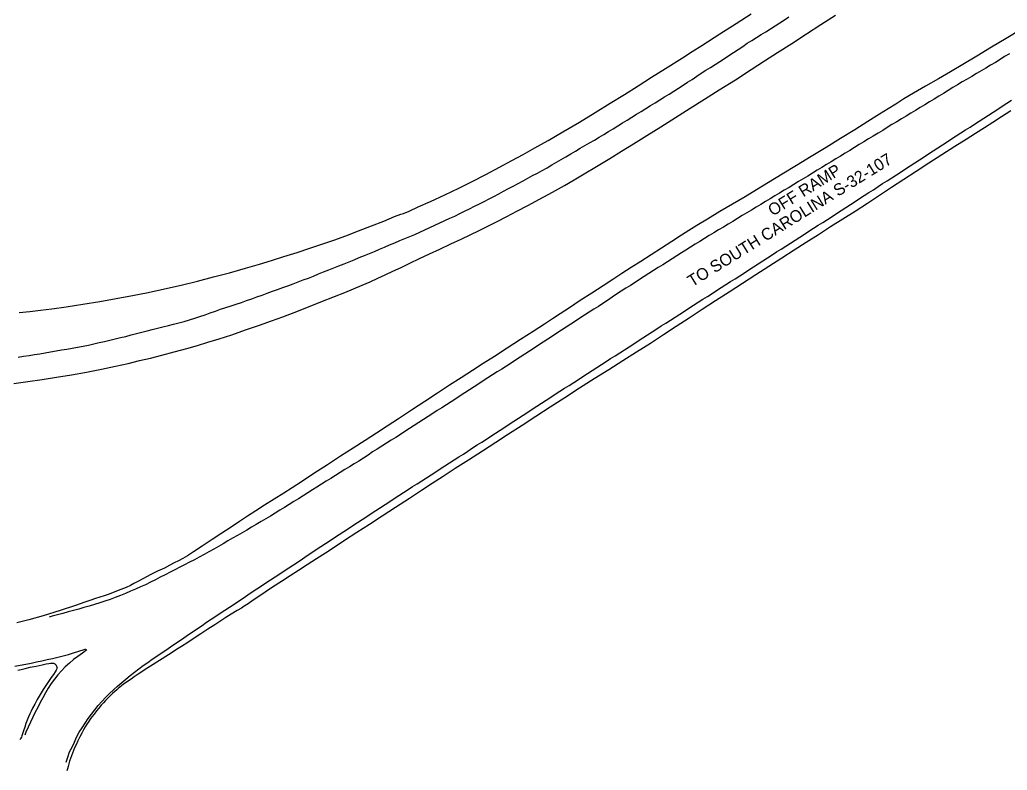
# Model space of a CAD drawing. Extents: x 1961683 to 1977751, y 798292 to 805767.
# Drawn here: x 1963000.6 to 1963450.9, y 799966.6 to 800308.9 of the extents above; entities that cross this region are included whole.
import ezdxf

# ---------------------------------------------------------------- set-up
doc = ezdxf.new("R2010")
doc.units = 0
for name, color, linetype in [('RD_EX_Conc', 7, 'Continuous'), ('RD_EX_Road', 7, 'Continuous'), ('RD_EX_Road_Paint', 7, 'Continuous'), ('RD_TX_RoadID', 7, 'Continuous')]:
    doc.layers.add(name, color=color, linetype=linetype)

msp = doc.modelspace()

# ---------------------------------------------------------------- linework, layer by layer
at = {"layer": 'RD_EX_Conc'}
msp.add_lwpolyline([(1962999.74, 800012.29), (1963001.27, 800012.63), (1963003.09, 800013.05), (1963005.34, 800013.57), (1963008.12, 800014.17), (1963010.78, 800014.72), (1963012.63, 800015.09), (1963013.86, 800015.32), (1963014.66, 800015.45), (1963015.21, 800015.5), (1963015.68, 800015.51), (1963015.89, 800015.47), (1963016.11, 800015.41), (1963016.34, 800015.3), (1963016.56, 800015.15), (1963016.95, 800014.84), (1963017.09, 800014.7), (1963017.19, 800014.58), (1963017.28, 800014.44), (1963017.45, 800014.09), (1963017.54, 800013.86), (1963017.6, 800013.62), (1963017.63, 800013.38), (1963017.61, 800013.13), (1963017.56, 800012.88), (1963017.45, 800012.6), (1963017.29, 800012.28), (1963016.78, 800011.48), (1963016.01, 800010.37), (1963014.94, 800008.87), (1963013.74, 800007.13), (1963012.58, 800005.35), (1963011.35, 800003.39), (1963009.97, 800001.13), (1963008.61, 799998.82), (1963007.44, 799996.71), (1963006.48, 799994.92), (1963005.79, 799993.58), (1963005.2, 799992.35), (1963004.58, 799990.92), (1963003.97, 799989.4), (1963003.42, 799987.9), (1963002.9, 799986.34), (1963002.38, 799984.65), (1963001.93, 799983.19), (1963001.63, 799982.31), (1963001.41, 799981.75), (1963001.19, 799981.28), (1963001.06, 799981.08), (1963000.93, 799980.91), (1963000.77, 799980.77), (1963000.6, 799980.65)], dxfattribs=at)
at = {"layer": 'RD_EX_Road'}
for points in [[(1962997.89, 800143), (1963004.37, 800143.91), (1963010.81, 800144.86), (1963017.35, 800145.88), (1963024.16, 800147.02), (1963031.04, 800148.25), (1963037.83, 800149.58), (1963044.25, 800150.93), (1963050.02, 800152.22), (1963055.3, 800153.46), (1963060.24, 800154.63), (1963065.34, 800155.91), (1963071.08, 800157.43), (1963076.77, 800159), (1963081.7, 800160.42), (1963086.46, 800161.86), (1963091.62, 800163.46), (1963097.31, 800165.3), (1963103.62, 800167.44), (1963109.88, 800169.61), (1963115.38, 800171.54), (1963120.54, 800173.42), (1963125.78, 800175.43), (1963131.46, 800177.68), (1963137.95, 800180.24), (1963144.11, 800182.67), (1963148.81, 800184.53), (1963152.77, 800186.15), (1963156.7, 800187.82), (1963160.46, 800189.47), (1963163.89, 800191.01), (1963167.24, 800192.56), (1963170.77, 800194.22), (1963174.52, 800195.99), (1963178.55, 800197.92), (1963182.85, 800199.97), (1963187.42, 800202.13), (1963192.2, 800204.37), (1963197.13, 800206.66), (1963201.87, 800208.87), (1963206.07, 800210.85), (1963210.05, 800212.78), (1963214.11, 800214.81), (1963218.31, 800216.95), (1963222.68, 800219.21), (1963227.31, 800221.63), (1963232.29, 800224.22), (1963237.65, 800227.07), (1963243.47, 800230.27), (1963248.98, 800233.37), (1963253.44, 800235.95), (1963257.95, 800238.63), (1963263.63, 800242.03), (1963269.62, 800245.65), (1963275.06, 800248.97), (1963280.51, 800252.34), (1963286.53, 800256.11), (1963292.96, 800260.14), (1963299.62, 800264.33), (1963306.33, 800268.54), (1963312.85, 800272.65), (1963319.59, 800276.92), (1963326.93, 800281.61), (1963334.06, 800286.19), (1963340.18, 800290.13), (1963346.1, 800293.96), (1963352.65, 800298.18), (1963359.39, 800302.53), (1963365.89, 800306.73), (1963372.53, 800311.05)], [(1963000.35, 800175.41), (1963005.22, 800175.93), (1963010.14, 800176.49), (1963015.32, 800177.12), (1963021.75, 800178), (1963029.4, 800179.15), (1963037.09, 800180.42), (1963044.63, 800181.78), (1963051.98, 800183.15), (1963059.17, 800184.55), (1963066.58, 800186.14), (1963074.2, 800187.94), (1963081.65, 800189.77), (1963088.91, 800191.63), (1963096.27, 800193.58), (1963103.6, 800195.61), (1963109.97, 800197.44), (1963115.42, 800199.1), (1963121.11, 800200.89), (1963127.15, 800202.84), (1963132.9, 800204.74), (1963138.34, 800206.59), (1963143.77, 800208.48), (1963149.28, 800210.44), (1963155.07, 800212.59), (1963161.07, 800214.91), (1963166.64, 800217.14), (1963171.48, 800219.13), (1963174.37, 800220.25), (1963175.6, 800220.63), (1963178.12, 800221.67), (1963182.35, 800223.56), (1963187.86, 800226.09), (1963194.39, 800229.13), (1963200.77, 800232.18), (1963206.88, 800235.21), (1963213.07, 800238.4), (1963219.32, 800241.7), (1963224.98, 800244.73), (1963230.11, 800247.48), (1963235.55, 800250.5), (1963241.49, 800253.88), (1963248.27, 800257.83), (1963255.78, 800262.26), (1963263.03, 800266.64), (1963269.88, 800270.86), (1963276.38, 800274.89), (1963282.57, 800278.77), (1963288.74, 800282.69), (1963295.13, 800286.77), (1963302.78, 800291.64), (1963307.15, 800294.41), (1963311.59, 800297.22), (1963319.83, 800302.47), (1963327.26, 800307.24), (1963334.15, 800311.7)], [(1963456.89, 800304.32), (1963450.33, 800300.42), (1963443.7, 800296.44), (1963437.01, 800292.34), (1963430.65, 800288.46), (1963425, 800285.17), (1963419.53, 800282.04), (1963413.67, 800278.67), (1963408.17, 800275.46), (1963403.78, 800272.81), (1963400.06, 800270.51), (1963396.57, 800268.32), (1963392.58, 800265.81), (1963387.36, 800262.52), (1963381.33, 800258.75), (1963374.9, 800254.79), (1963368.25, 800250.7), (1963361.53, 800246.56), (1963354.82, 800242.45), (1963348.19, 800238.47), (1963342, 800234.75), (1963336.58, 800231.42), (1963331.33, 800228.21), (1963325.65, 800224.83), (1963319.86, 800221.41), (1963314.24, 800218.05), (1963309.36, 800215.08), (1963305.74, 800212.83), (1963302.3, 800210.63), (1963297.97, 800207.81), (1963293.2, 800204.7), (1963288.45, 800201.65), (1963283.83, 800198.7), (1963279.44, 800195.9), (1963275.2, 800193.2), (1963271.06, 800190.52), (1963266.6, 800187.64), (1963261.41, 800184.3), (1963256.1, 800180.84), (1963251.25, 800177.59), (1963247.03, 800174.73), (1963243.6, 800172.46), (1963239.89, 800170.05), (1963234.78, 800166.81), (1963228.9, 800163.06), (1963222.84, 800159.15), (1963217.03, 800155.39), (1963211.91, 800152.09), (1963207.01, 800148.95), (1963201.87, 800145.67), (1963196.54, 800142.24), (1963191.05, 800138.65), (1963185.31, 800134.86), (1963179.2, 800130.85), (1963173.29, 800126.98), (1963168.13, 800123.6), (1963163.23, 800120.39), (1963158.08, 800117.04), (1963152.65, 800113.52), (1963146.94, 800109.85), (1963140.96, 800105.99), (1963134.75, 800101.93), (1963129.1, 800098.25), (1963124.83, 800095.49), (1963121, 800093.06), (1963116.67, 800090.34), (1963112.27, 800087.56), (1963108.26, 800084.98), (1963104.48, 800082.51), (1963100.78, 800080.08), (1963096.95, 800077.55), (1963092.75, 800074.79), (1963088.33, 800071.86), (1963083.82, 800068.86), (1963079.85, 800066.25), (1963077.06, 800064.49), (1963074.93, 800063.25), (1963072.98, 800062.18), (1963071.07, 800061.18), (1963069.07, 800060.11), (1963066.65, 800058.87), (1963063.47, 800057.36), (1963060.08, 800055.73), (1963056.98, 800054.11), (1963054.43, 800052.72), (1963052.65, 800051.74), (1963051.06, 800050.93), (1963049.08, 800050.02), (1963046.72, 800049.04), (1963044.01, 800047.98), (1963041.35, 800046.98), (1963039.09, 800046.19), (1963037.09, 800045.52), (1963035.18, 800044.89), (1963033.03, 800044.16), (1963030.33, 800043.24), (1963026.01, 800041.79), (1963018.99, 800039.52), (1963011.24, 800037.12), (1963004.74, 800035.27), (1962999.34, 800033.91)], [(1963452.55, 800267.45), (1963448.32, 800264.71), (1963444.28, 800262.09), (1963440.47, 800259.63), (1963436.46, 800257.1), (1963432.09, 800254.38), (1963426.95, 800251.11), (1963421.07, 800247.3), (1963415.17, 800243.48), (1963409.38, 800239.73), (1963403.71, 800236.04), (1963398.15, 800232.4), (1963392.63, 800228.77), (1963387.12, 800225.16), (1963381.55, 800221.55), (1963375.91, 800217.97), (1963370.3, 800214.42), (1963364.75, 800210.9), (1963359.23, 800207.41), (1963353.73, 800203.92), (1963348.04, 800200.26), (1963342.17, 800196.43), (1963336.21, 800192.56), (1963330.19, 800188.66), (1963324.09, 800184.7), (1963317.91, 800180.68), (1963311.82, 800176.71), (1963305.85, 800172.82), (1963299.98, 800168.99), (1963294.17, 800165.19), (1963288.15, 800161.31), (1963281.89, 800157.35), (1963275.56, 800153.36), (1963269.16, 800149.33), (1963262.61, 800145.16), (1963255.91, 800140.86), (1963249.2, 800136.53), (1963242.54, 800132.22), (1963236, 800127.99), (1963229.63, 800123.89), (1963223.54, 800119.96), (1963217.67, 800116.15), (1963211.55, 800112.19), (1963205.18, 800108.08), (1963199.21, 800104.21), (1963193.73, 800100.65), (1963188.65, 800097.35), (1963183.81, 800094.21), (1963178.27, 800090.56), (1963172.02, 800086.41), (1963165.91, 800082.45), (1963160.05, 800078.74), (1963154.29, 800075.04), (1963148.71, 800071.39), (1963143.96, 800068.27), (1963140.02, 800065.66), (1963135.96, 800063), (1963131.72, 800060.25), (1963127.71, 800057.68), (1963123.95, 800055.31), (1963120, 800052.77), (1963115.93, 800050.1), (1963112.47, 800047.8), (1963109.66, 800045.91), (1963107.09, 800044.16), (1963104.75, 800042.55), (1963103, 800041.39), (1963101.73, 800040.61), (1963099.77, 800039.43), (1963097.1, 800037.82), (1963094.58, 800036.25), (1963092.26, 800034.75), (1963089.54, 800032.97), (1963086.37, 800030.91), (1963083.24, 800028.87), (1963080.21, 800026.88), (1963077.25, 800024.95), (1963074.42, 800023.11), (1963072.14, 800021.63), (1963070.06, 800020.28), (1963065.61, 800017.45), (1963059.08, 800013.3), (1963054.66, 800010.46), (1963052.75, 800009.17), (1963051.39, 800008.24), (1963050.23, 800007.44), (1963049.09, 800006.64), (1963047.96, 800005.84), (1963046.99, 800005.12), (1963046.2, 800004.5), (1963045.49, 800003.92), (1963044.82, 800003.34), (1963043.95, 800002.56), (1963042.89, 800001.58), (1963041.82, 800000.52), (1963040.77, 799999.43), (1963039.77, 799998.38), (1963038.8, 799997.37), (1963037.78, 799996.26), (1963036.69, 799995.01), (1963035.59, 799993.68), (1963034.49, 799992.28), (1963033.53, 799991.01), (1963032.73, 799989.87), (1963031.98, 799988.76), (1963031.26, 799987.64), (1963030.51, 799986.4), (1963029.73, 799985.02), (1963028.9, 799983.49), (1963028.03, 799981.82), (1963027.16, 799980.06), (1963026.33, 799978.28), (1963025.64, 799976.78), (1963025.09, 799975.57), (1963024.62, 799974.4), (1963024.2, 799973.23), (1963023.78, 799972), (1963023.38, 799970.72), (1963023.01, 799969.48), (1963022.66, 799968.32), (1963022.38, 799967.3), (1963022.15, 799966.43)]]:
    msp.add_lwpolyline(points, dxfattribs=at)
at = {"layer": 'RD_EX_Road_Paint'}
for points in [[(1962999.91, 800155.08), (1963002.39, 800155.44), (1963004.86, 800155.8), (1963007.33, 800156.19), (1963009.79, 800156.61), (1963012.26, 800157.04), (1963014.72, 800157.46), (1963017.18, 800157.89), (1963019.65, 800158.32), (1963022.11, 800158.75), (1963024.57, 800159.19), (1963027.03, 800159.63), (1963029.49, 800160.07), (1963031.94, 800160.56), (1963034.39, 800161.08), (1963036.82, 800161.66), (1963039.25, 800162.24), (1963041.69, 800162.79), (1963044.13, 800163.34), (1963046.56, 800163.94), (1963048.98, 800164.54), (1963051.39, 800165.21), (1963053.8, 800165.89), (1963056.22, 800166.5), (1963058.65, 800167.1), (1963061.08, 800167.68), (1963063.51, 800168.25), (1963065.94, 800168.83), (1963068.38, 800169.41), (1963070.8, 800170.03), (1963073.22, 800170.66), (1963075.61, 800171.37), (1963078.01, 800172.09), (1963080.39, 800172.85), (1963082.77, 800173.6), (1963085.14, 800174.41), (1963087.51, 800175.22), (1963089.85, 800176.08), (1963092.2, 800176.95), (1963094.57, 800177.73), (1963096.95, 800178.5), (1963099.33, 800179.27), (1963101.71, 800180.03), (1963104.07, 800180.85), (1963106.43, 800181.67), (1963108.79, 800182.49), (1963111.16, 800183.31), (1963113.49, 800184.2), (1963115.83, 800185.1), (1963118.18, 800185.93), (1963120.54, 800186.77), (1963122.89, 800187.6), (1963125.25, 800188.44), (1963127.58, 800189.34), (1963129.92, 800190.24), (1963132.25, 800191.12), (1963134.59, 800192), (1963136.9, 800192.98), (1963139.2, 800193.95), (1963141.53, 800194.86), (1963143.85, 800195.77), (1963146.17, 800196.71), (1963148.49, 800197.65), (1963150.81, 800198.58), (1963153.13, 800199.51), (1963155.45, 800200.45), (1963157.76, 800201.39), (1963160.07, 800202.34), (1963162.39, 800203.29), (1963164.69, 800204.27), (1963166.99, 800205.25), (1963169.29, 800206.22), (1963171.6, 800207.18), (1963173.89, 800208.19), (1963176.18, 800209.19), (1963178.5, 800210.12), (1963180.82, 800211.05), (1963183.08, 800212.12), (1963185.34, 800213.19), (1963187.62, 800214.21), (1963189.9, 800215.22), (1963192.17, 800216.29), (1963194.43, 800217.35), (1963196.71, 800218.38), (1963198.98, 800219.42), (1963201.23, 800220.52), (1963203.47, 800221.62), (1963205.71, 800222.73), (1963207.95, 800223.85), (1963210.18, 800224.97), (1963212.42, 800226.09), (1963214.64, 800227.24), (1963216.86, 800228.38), (1963219.07, 800229.56), (1963221.27, 800230.73), (1963223.47, 800231.92), (1963225.67, 800233.11), (1963227.89, 800234.27), (1963230.1, 800235.43), (1963232.29, 800236.63), (1963234.49, 800237.83), (1963236.68, 800239.03), (1963238.87, 800240.24), (1963241.04, 800241.47), (1963243.22, 800242.7), (1963245.37, 800243.97), (1963247.52, 800245.25), (1963249.69, 800246.49), (1963251.86, 800247.74), (1963254, 800249.02), (1963256.15, 800250.31), (1963258.31, 800251.56), (1963260.47, 800252.82), (1963262.62, 800254.09), (1963264.78, 800255.36), (1963266.92, 800256.65), (1963269.05, 800257.95), (1963271.18, 800259.26), (1963273.31, 800260.58), (1963275.44, 800261.88), (1963277.57, 800263.19), (1963279.69, 800264.51), (1963281.82, 800265.83), (1963283.94, 800267.15), (1963286.06, 800268.47), (1963288.18, 800269.79), (1963290.31, 800271.12), (1963292.44, 800272.41), (1963294.58, 800273.71), (1963296.68, 800275.06), (1963298.79, 800276.41), (1963300.91, 800277.73), (1963303.04, 800279.04), (1963305.14, 800280.4), (1963307.24, 800281.76), (1963309.31, 800283.15), (1963311.39, 800284.54), (1963313.5, 800285.88), (1963315.61, 800287.22), (1963317.7, 800288.59), (1963319.79, 800289.96), (1963321.9, 800291.31), (1963324, 800292.67), (1963326.11, 800294.01), (1963328.21, 800295.36), (1963330.27, 800296.78), (1963332.33, 800298.19), (1963334.45, 800299.52), (1963336.57, 800300.85), (1963338.7, 800302.16), (1963340.83, 800303.47), (1963342.92, 800304.84), (1963345.01, 800306.21), (1963347.13, 800307.54), (1963349.24, 800308.87), (1963351.33, 800310.25)], [(1963451.84, 800293.41), (1963449.7, 800292.12), (1963447.58, 800290.79), (1963445.46, 800289.47), (1963443.31, 800288.19), (1963441.17, 800286.91), (1963439.01, 800285.64), (1963436.86, 800284.37), (1963434.7, 800283.11), (1963432.54, 800281.85), (1963430.39, 800280.57), (1963428.25, 800279.28), (1963426.11, 800277.98), (1963423.98, 800276.68), (1963421.85, 800275.37), (1963419.72, 800274.06), (1963417.59, 800272.75), (1963415.46, 800271.45), (1963413.32, 800270.16), (1963411.17, 800268.87), (1963409.03, 800267.58), (1963406.89, 800266.29), (1963404.75, 800265.01), (1963402.6, 800263.72), (1963400.46, 800262.43), (1963398.32, 800261.14), (1963396.2, 800259.81), (1963394.09, 800258.47), (1963391.95, 800257.18), (1963389.81, 800255.88), (1963387.68, 800254.59), (1963385.54, 800253.29), (1963383.41, 800251.98), (1963381.28, 800250.67), (1963379.14, 800249.38), (1963377.01, 800248.08), (1963374.88, 800246.76), (1963372.75, 800245.45), (1963370.62, 800244.15), (1963368.48, 800242.85), (1963366.34, 800241.56), (1963364.21, 800240.26), (1963362.07, 800238.96), (1963359.94, 800237.66), (1963357.79, 800236.38), (1963355.65, 800235.09), (1963353.51, 800233.79), (1963351.38, 800232.48), (1963349.23, 800231.2), (1963347.09, 800229.91), (1963344.96, 800228.61), (1963342.83, 800227.3), (1963340.7, 800226), (1963338.56, 800224.69), (1963336.42, 800223.41), (1963334.27, 800222.13), (1963332.11, 800220.88), (1963329.95, 800219.62), (1963327.82, 800218.3), (1963325.7, 800216.98), (1963323.57, 800215.68), (1963321.43, 800214.37), (1963319.29, 800213.08), (1963317.16, 800211.78), (1963315.02, 800210.49), (1963312.88, 800209.19), (1963310.76, 800207.87), (1963308.63, 800206.55), (1963306.51, 800205.23), (1963304.39, 800203.91), (1963302.28, 800202.57), (1963300.16, 800201.24), (1963298.04, 800199.91), (1963295.93, 800198.58), (1963293.82, 800197.23), (1963291.72, 800195.89), (1963289.6, 800194.55), (1963287.49, 800193.21), (1963285.38, 800191.88), (1963283.27, 800190.54), (1963281.18, 800189.16), (1963279.1, 800187.78), (1963276.99, 800186.44), (1963274.88, 800185.09), (1963272.79, 800183.72), (1963270.71, 800182.34), (1963268.63, 800180.94), (1963266.56, 800179.55), (1963264.44, 800178.21), (1963262.33, 800176.87), (1963260.24, 800175.52), (1963258.14, 800174.16), (1963256.04, 800172.79), (1963253.95, 800171.42), (1963251.87, 800170.04), (1963249.78, 800168.67), (1963247.68, 800167.31), (1963245.58, 800165.95), (1963243.47, 800164.61), (1963241.36, 800163.27), (1963239.28, 800161.88), (1963237.2, 800160.49), (1963235.11, 800159.12), (1963233.02, 800157.76), (1963230.92, 800156.39), (1963228.83, 800155.03), (1963226.74, 800153.66), (1963224.64, 800152.3), (1963222.53, 800150.96), (1963220.42, 800149.62), (1963218.31, 800148.28), (1963216.2, 800146.94), (1963214.09, 800145.59), (1963211.99, 800144.24), (1963209.91, 800142.85), (1963207.81, 800141.49), (1963205.71, 800140.15), (1963203.6, 800138.8), (1963201.49, 800137.45), (1963199.4, 800136.09), (1963197.31, 800134.71), (1963195.22, 800133.35), (1963193.12, 800131.99), (1963191.02, 800130.64), (1963188.91, 800129.29), (1963186.81, 800127.94), (1963184.7, 800126.59), (1963182.59, 800125.25), (1963180.48, 800123.92), (1963178.38, 800122.56), (1963176.28, 800121.2), (1963174.19, 800119.83), (1963172.09, 800118.47), (1963169.99, 800117.12), (1963167.88, 800115.77), (1963165.76, 800114.46), (1963163.63, 800113.15), (1963161.53, 800111.79), (1963159.45, 800110.41), (1963157.37, 800109.02), (1963155.29, 800107.63), (1963153.15, 800106.33), (1963151, 800105.05), (1963148.88, 800103.74), (1963146.76, 800102.41), (1963144.64, 800101.09), (1963142.52, 800099.76), (1963140.4, 800098.44), (1963138.28, 800097.11), (1963136.16, 800095.79), (1963134.04, 800094.46), (1963131.92, 800093.13), (1963129.8, 800091.81), (1963127.68, 800090.48), (1963125.56, 800089.16), (1963123.44, 800087.83), (1963121.32, 800086.51), (1963119.21, 800085.18), (1963117.08, 800083.86), (1963114.94, 800082.57), (1963112.8, 800081.28), (1963110.65, 800080.01), (1963108.5, 800078.73), (1963106.36, 800077.44), (1963104.21, 800076.16), (1963102.03, 800074.94), (1963099.84, 800073.73), (1963097.68, 800072.47), (1963095.53, 800071.2), (1963093.36, 800069.95), (1963091.2, 800068.71), (1963089.06, 800067.41), (1963086.88, 800066.19), (1963084.69, 800064.98), (1963082.5, 800063.78), (1963080.27, 800062.64), (1963078.04, 800061.51), (1963075.82, 800060.37), (1963073.59, 800059.23), (1963071.37, 800058.09), (1963069.14, 800056.95), (1963066.92, 800055.81), (1963064.69, 800054.67), (1963062.47, 800053.54), (1963060.24, 800052.4), (1963058.01, 800051.26), (1963055.73, 800050.24), (1963053.44, 800049.24), (1963051.15, 800048.25), (1963048.85, 800047.26), (1963046.53, 800046.33), (1963044.21, 800045.41), (1963041.85, 800044.56), (1963039.5, 800043.73), (1963037.12, 800042.97), (1963034.72, 800042.24), (1963032.32, 800041.54), (1963029.92, 800040.85), (1963027.52, 800040.16), (1963025.11, 800039.48), (1963022.71, 800038.81), (1963020.29, 800038.15), (1963017.88, 800037.5), (1963015.46, 800036.85), (1963014.03, 800036.47)], [(1963021.77, 799970.24), (1963022.62, 799972.59), (1963023.39, 799974.96), (1963024.5, 799977.2), (1963025.52, 799979.47), (1963026.55, 799981.75), (1963027.79, 799983.92), (1963029.12, 799986.03), (1963030.5, 799988.11), (1963031.9, 799990.18), (1963033.34, 799992.22), (1963034.87, 799994.2), (1963036.43, 799996.15), (1963038.09, 799998.02), (1963039.78, 799999.85), (1963041.58, 800001.59), (1963043.4, 800003.31), (1963045.25, 800004.98), (1963047.13, 800006.63), (1963049.05, 800008.23), (1963050.98, 800009.82), (1963052.95, 800011.36), (1963054.93, 800012.88), (1963056.94, 800014.36), (1963058.97, 800015.82), (1963061.03, 800017.24), (1963063.09, 800018.65), (1963065.16, 800020.06), (1963067.23, 800021.46), (1963069.31, 800022.85), (1963071.38, 800024.25), (1963073.45, 800025.65), (1963075.51, 800027.06), (1963077.57, 800028.48), (1963079.63, 800029.9), (1963081.69, 800031.31), (1963083.76, 800032.72), (1963085.84, 800034.11), (1963087.91, 800035.5), (1963090, 800036.88), (1963092.08, 800038.27), (1963094.15, 800039.66), (1963096.23, 800041.05), (1963098.32, 800042.42), (1963100.41, 800043.8), (1963102.49, 800045.18), (1963104.56, 800046.57), (1963106.63, 800047.98), (1963108.7, 800049.38), (1963110.79, 800050.76), (1963112.87, 800052.14), (1963114.95, 800053.52), (1963117.04, 800054.89), (1963119.14, 800056.25), (1963121.24, 800057.6), (1963123.33, 800058.97), (1963125.42, 800060.35), (1963127.5, 800061.74), (1963129.57, 800063.13), (1963131.66, 800064.51), (1963133.75, 800065.88), (1963135.84, 800067.26), (1963137.93, 800068.63), (1963140.02, 800069.99), (1963142.11, 800071.36), (1963144.19, 800072.75), (1963146.28, 800074.13), (1963148.36, 800075.51), (1963150.46, 800076.87), (1963152.56, 800078.23), (1963154.66, 800079.58), (1963156.74, 800080.96), (1963158.83, 800082.34), (1963160.93, 800083.7), (1963163.02, 800085.06), (1963165.12, 800086.43), (1963167.21, 800087.79), (1963169.3, 800089.17), (1963171.39, 800090.54), (1963173.49, 800091.9), (1963175.58, 800093.26), (1963177.68, 800094.62), (1963179.77, 800095.98), (1963181.87, 800097.34), (1963183.97, 800098.7), (1963186.08, 800100.05), (1963188.18, 800101.4), (1963190.27, 800102.78), (1963192.36, 800104.14), (1963194.47, 800105.48), (1963196.58, 800106.83), (1963198.68, 800108.19), (1963200.78, 800109.54), (1963202.89, 800110.87), (1963205, 800112.22), (1963207.07, 800113.61), (1963209.16, 800114.99), (1963211.27, 800116.34), (1963213.37, 800117.68), (1963215.47, 800119.04), (1963217.57, 800120.4), (1963219.67, 800121.76), (1963221.76, 800123.13), (1963223.85, 800124.5), (1963225.95, 800125.86), (1963228.05, 800127.21), (1963230.15, 800128.56), (1963232.25, 800129.93), (1963234.34, 800131.29), (1963236.45, 800132.64), (1963238.55, 800134), (1963240.64, 800135.37), (1963242.73, 800136.74), (1963244.82, 800138.11), (1963246.91, 800139.48), (1963249.01, 800140.83), (1963251.12, 800142.18), (1963253.22, 800143.53), (1963255.33, 800144.88), (1963257.42, 800146.25), (1963259.51, 800147.61), (1963261.61, 800148.97), (1963263.71, 800150.33), (1963265.82, 800151.67), (1963267.93, 800153.02), (1963270.03, 800154.37), (1963272.14, 800155.72), (1963274.24, 800157.08), (1963276.34, 800158.43), (1963278.46, 800159.75), (1963280.57, 800161.09), (1963282.66, 800162.45), (1963284.76, 800163.82), (1963286.85, 800165.19), (1963288.94, 800166.56), (1963291.04, 800167.92), (1963293.14, 800169.27), (1963295.24, 800170.62), (1963297.35, 800171.98), (1963299.45, 800173.33), (1963301.55, 800174.68), (1963303.66, 800176.03), (1963305.76, 800177.38), (1963307.87, 800178.73), (1963309.97, 800180.08), (1963312.07, 800181.43), (1963314.18, 800182.78), (1963316.28, 800184.13), (1963318.38, 800185.48), (1963320.49, 800186.82), (1963322.6, 800188.16), (1963324.72, 800189.5), (1963326.83, 800190.84), (1963328.92, 800192.2), (1963331.02, 800193.57), (1963333.12, 800194.92), (1963335.22, 800196.27), (1963337.32, 800197.62), (1963339.43, 800198.98), (1963341.53, 800200.33), (1963343.63, 800201.68), (1963345.74, 800203.02), (1963347.85, 800204.36), (1963349.96, 800205.71), (1963352.07, 800207.05), (1963354.16, 800208.42), (1963356.25, 800209.79), (1963358.36, 800211.13), (1963360.46, 800212.48), (1963362.57, 800213.83), (1963364.67, 800215.18), (1963366.78, 800216.53), (1963368.88, 800217.88), (1963370.98, 800219.24), (1963373.08, 800220.6), (1963375.18, 800221.95), (1963377.29, 800223.3), (1963379.38, 800224.66), (1963381.48, 800226.02), (1963383.58, 800227.38), (1963385.68, 800228.74), (1963387.78, 800230.09), (1963389.88, 800231.44), (1963391.97, 800232.81), (1963394.07, 800234.18), (1963396.16, 800235.54), (1963398.26, 800236.9), (1963400.35, 800238.28), (1963402.44, 800239.64), (1963404.55, 800240.99), (1963406.65, 800242.34), (1963408.75, 800243.7), (1963410.85, 800245.06), (1963412.94, 800246.42), (1963415.04, 800247.78), (1963417.13, 800249.16), (1963419.22, 800250.53), (1963421.33, 800251.87), (1963423.43, 800253.22), (1963425.52, 800254.59), (1963427.61, 800255.96), (1963429.72, 800257.31), (1963431.82, 800258.66), (1963433.91, 800260.02), (1963436.01, 800261.38), (1963438.11, 800262.74), (1963440.21, 800264.1), (1963442.3, 800265.46), (1963444.4, 800266.83), (1963446.51, 800268.17), (1963448.61, 800269.52), (1963450.71, 800270.88), (1963452.82, 800272.23)], [(1962998.4, 800014.13), (1963000.87, 800014.55), (1963003.33, 800014.97), (1963005.78, 800015.49), (1963008.22, 800016.02), (1963010.66, 800016.56), (1963013.1, 800017.09), (1963015.54, 800017.65), (1963017.98, 800018.21), (1963020.4, 800018.83), (1963022.81, 800019.49), (1963025.19, 800020.24), (1963027.58, 800020.99), (1963029.96, 800021.74), (1963030.79, 800022)], [(1963031.2, 800021.5), (1963029.17, 800020.04), (1963027.14, 800018.57), (1963025.11, 800017.12), (1963023.24, 800015.47), (1963021.32, 800013.87), (1963019.66, 800012.01), (1963018.05, 800010.09), (1963016.45, 800008.18), (1963014.97, 800006.17), (1963013.6, 800004.08), (1963012.35, 800001.91), (1963011.16, 799999.72), (1963009.99, 799997.51), (1963008.84, 799995.29), (1963007.72, 799993.06), (1963006.67, 799990.79), (1963005.57, 799988.54), (1963004.45, 799986.31), (1963003.47, 799984.01), (1963002.96, 799982.7)]]:
    msp.add_lwpolyline(points, dxfattribs=at)

# ---------------------------------------------------------------- texts
at = {"layer": 'RD_TX_RoadID'}
for s, p in [('TO SOUTH CAROLINA S-32-107', (1963307.22, 800186.89)), ('OFF RAMP', (1963343.92, 800219.19))]:
    msp.add_text(s, height=5.4, rotation=31.8174, dxfattribs=at).set_placement(p)

doc.saveas('drawing.dxf')
